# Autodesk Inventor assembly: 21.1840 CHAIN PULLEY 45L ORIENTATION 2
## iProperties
Created: 2007-05
Part Number: 21.1840 CHAIN PULLEY 45L ORIENTATION 2
Document SubType Name: Assembly
Designer: Andy Moles
Author: Andy Moles
